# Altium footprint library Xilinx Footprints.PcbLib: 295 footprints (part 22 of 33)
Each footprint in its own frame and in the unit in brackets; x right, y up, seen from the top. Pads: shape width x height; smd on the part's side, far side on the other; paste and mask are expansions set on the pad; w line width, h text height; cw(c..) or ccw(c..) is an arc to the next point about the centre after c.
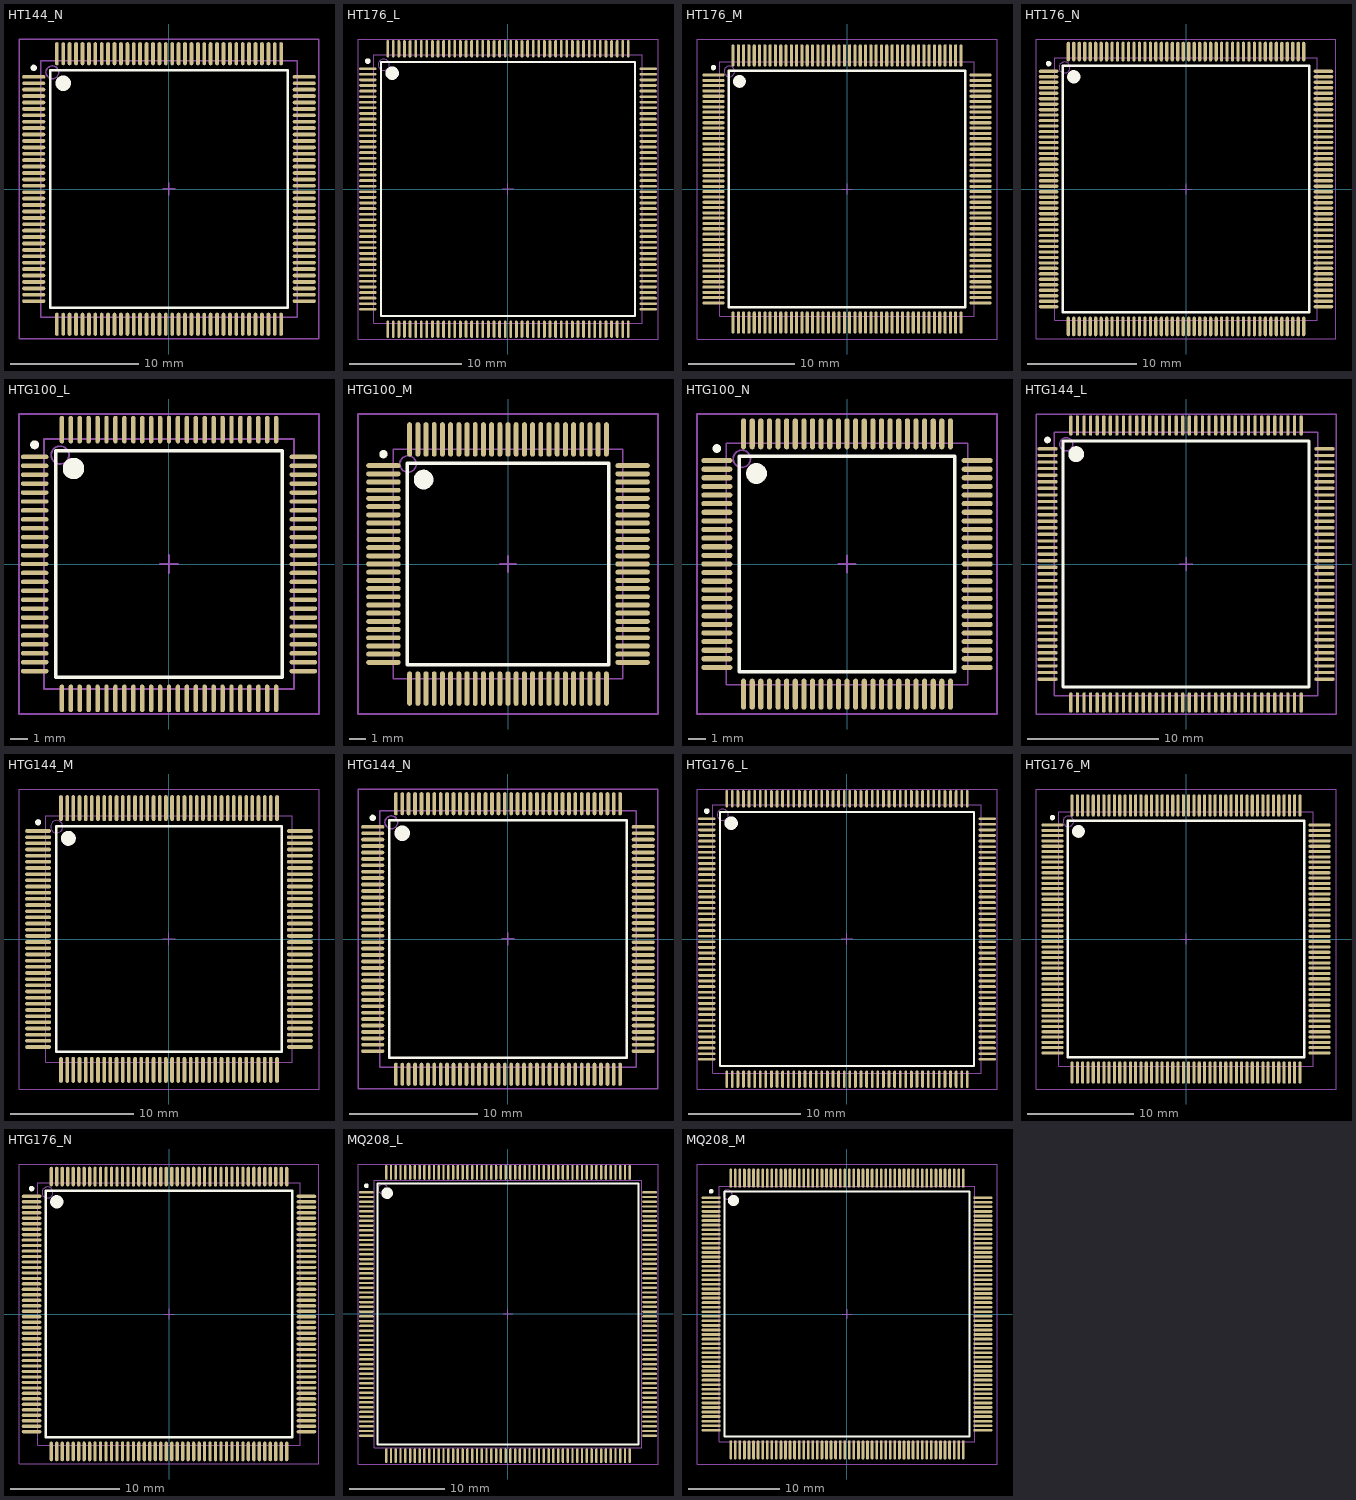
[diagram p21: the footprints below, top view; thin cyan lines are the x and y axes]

## HT144_N [mm] "144-Pin Heat Sink Thin Quad Flat Pack (HT144), IPC Medium Density"
height 1.6
pads (144):
  oval 1.8x0.3 smd: 1(-10.55,8.75) 2(-10.55,8.25) 3(-10.55,7.75) 4(-10.55,7.25) 5(-10.55,6.75) 6(-10.55,6.25) 7(-10.55,5.75) 8(-10.55,5.25) 9(-10.55,4.75) 10(-10.55,4.25) 11(-10.55,3.75) 12(-10.55,3.25) 13(-10.55,2.75) 14(-10.55,2.25) 15(-10.55,1.75) 16(-10.55,1.25) 17(-10.55,0.75) 18(-10.55,0.25) 19(-10.55,-0.25) 20(-10.55,-0.75) 21(-10.55,-1.25) 22(-10.55,-1.75) 23(-10.55,-2.25) 24(-10.55,-2.75) 25(-10.55,-3.25) 26(-10.55,-3.75) 27(-10.55,-4.25) 28(-10.55,-4.75) 29(-10.55,-5.25) 30(-10.55,-5.75) 31(-10.55,-6.25) 32(-10.55,-6.75) 33(-10.55,-7.25) 34(-10.55,-7.75) 35(-10.55,-8.25) 36(-10.55,-8.75) 73(10.55,-8.75) 74(10.55,-8.25) 75(10.55,-7.75) 76(10.55,-7.25) 77(10.55,-6.75) 78(10.55,-6.25) 79(10.55,-5.75) 80(10.55,-5.25) 81(10.55,-4.75) 82(10.55,-4.25) 83(10.55,-3.75) 84(10.55,-3.25) 85(10.55,-2.75) 86(10.55,-2.25) 87(10.55,-1.75) 88(10.55,-1.25) 89(10.55,-0.75) 90(10.55,-0.25) 91(10.55,0.25) 92(10.55,0.75) 93(10.55,1.25) 94(10.55,1.75) 95(10.55,2.25) 96(10.55,2.75) 97(10.55,3.25) 98(10.55,3.75) 99(10.55,4.25) 100(10.55,4.75) 101(10.55,5.25) 102(10.55,5.75) 103(10.55,6.25) 104(10.55,6.75) 105(10.55,7.25) 106(10.55,7.75) 107(10.55,8.25) 108(10.55,8.75)
  oval 0.3x1.8 smd: 37(-8.75,-10.55) 38(-8.25,-10.55) 39(-7.75,-10.55) 40(-7.25,-10.55) 41(-6.75,-10.55) 42(-6.25,-10.55) 43(-5.75,-10.55) 44(-5.25,-10.55) 45(-4.75,-10.55) 46(-4.25,-10.55) 47(-3.75,-10.55) 48(-3.25,-10.55) 49(-2.75,-10.55) 50(-2.25,-10.55) 51(-1.75,-10.55) 52(-1.25,-10.55) 53(-0.75,-10.55) 54(-0.25,-10.55) 55(0.25,-10.55) 56(0.75,-10.55) 57(1.25,-10.55) 58(1.75,-10.55) 59(2.25,-10.55) 60(2.75,-10.55) 61(3.25,-10.55) 62(3.75,-10.55) 63(4.25,-10.55) 64(4.75,-10.55) 65(5.25,-10.55) 66(5.75,-10.55) 67(6.25,-10.55) 68(6.75,-10.55) 69(7.25,-10.55) 70(7.75,-10.55) 71(8.25,-10.55) 72(8.75,-10.55) 109(8.75,10.55) 110(8.25,10.55) 111(7.75,10.55) 112(7.25,10.55) 113(6.75,10.55) 114(6.25,10.55) 115(5.75,10.55) 116(5.25,10.55) 117(4.75,10.55) 118(4.25,10.55) 119(3.75,10.55) 120(3.25,10.55) 121(2.75,10.55) 122(2.25,10.55) 123(1.75,10.55) 124(1.25,10.55) 125(0.75,10.55) 126(0.25,10.55) 127(-0.25,10.55) 128(-0.75,10.55) 129(-1.25,10.55) 130(-1.75,10.55) 131(-2.25,10.55) 132(-2.75,10.55) 133(-3.25,10.55) 134(-3.75,10.55) 135(-4.25,10.55) 136(-4.75,10.55) 137(-5.25,10.55) 138(-5.75,10.55) 139(-6.25,10.55) 140(-6.75,10.55) 141(-7.25,10.55) 142(-7.75,10.55) 143(-8.25,10.55) 144(-8.75,10.55)
Top Overlay:
  circle w0.25: c-10.55,9.45 r0.125
  circle w0.6: c-8.25,8.25 r0.3
  lines w0.2: -9.25,-9.25 -9.25,9.25 9.25,9.25 9.25,-9.25 -9.25,-9.25
Mechanical 13:
  circle w0.1: c-9.1,9.1 r0.5
  lines w0.1: -10,-10 -10,10 10,10 10,-10 -10,-10
Mechanical 15:
  lines w0.1: -0.5,0 0.5,0 ; 0,-0.5 0,0.5 ; -11.7,-11.7 -11.7,11.7 11.7,11.7 11.7,-11.7 -11.7,-11.7
3D body: height 1.6, standoff 0, extent -10,-10 10,10

## HT176_L [mm] "176-Pin Heat Sink Thin Quad Flat Pack (HT176), IPC High Density"
height 1.6
pads (176):
  oval 1.55x0.25 smd: 1(-12.525,10.75) 2(-12.525,10.25) 3(-12.525,9.75) 4(-12.525,9.25) 5(-12.525,8.75) 6(-12.525,8.25) 7(-12.525,7.75) 8(-12.525,7.25) 9(-12.525,6.75) 10(-12.525,6.25) 11(-12.525,5.75) 12(-12.525,5.25) 13(-12.525,4.75) 14(-12.525,4.25) 15(-12.525,3.75) 16(-12.525,3.25) 17(-12.525,2.75) 18(-12.525,2.25) 19(-12.525,1.75) 20(-12.525,1.25) 21(-12.525,0.75) 22(-12.525,0.25) 23(-12.525,-0.25) 24(-12.525,-0.75) 25(-12.525,-1.25) 26(-12.525,-1.75) 27(-12.525,-2.25) 28(-12.525,-2.75) 29(-12.525,-3.25) 30(-12.525,-3.75) 31(-12.525,-4.25) 32(-12.525,-4.75) 33(-12.525,-5.25) 34(-12.525,-5.75) 35(-12.525,-6.25) 36(-12.525,-6.75) 37(-12.525,-7.25) 38(-12.525,-7.75) 39(-12.525,-8.25) 40(-12.525,-8.75) 41(-12.525,-9.25) 42(-12.525,-9.75) 43(-12.525,-10.25) 44(-12.525,-10.75) 89(12.525,-10.75) 90(12.525,-10.25) 91(12.525,-9.75) 92(12.525,-9.25) 93(12.525,-8.75) 94(12.525,-8.25) 95(12.525,-7.75) 96(12.525,-7.25) 97(12.525,-6.75) 98(12.525,-6.25) 99(12.525,-5.75) 100(12.525,-5.25) 101(12.525,-4.75) 102(12.525,-4.25) 103(12.525,-3.75) 104(12.525,-3.25) 105(12.525,-2.75) 106(12.525,-2.25) 107(12.525,-1.75) 108(12.525,-1.25) 109(12.525,-0.75) 110(12.525,-0.25) 111(12.525,0.25) 112(12.525,0.75) 113(12.525,1.25) 114(12.525,1.75) 115(12.525,2.25) 116(12.525,2.75) 117(12.525,3.25) 118(12.525,3.75) 119(12.525,4.25) 120(12.525,4.75) 121(12.525,5.25) 122(12.525,5.75) 123(12.525,6.25) 124(12.525,6.75) 125(12.525,7.25) 126(12.525,7.75) 127(12.525,8.25) 128(12.525,8.75) 129(12.525,9.25) 130(12.525,9.75) 131(12.525,10.25) 132(12.525,10.75)
  oval 0.25x1.55 smd: 45(-10.75,-12.525) 46(-10.25,-12.525) 47(-9.75,-12.525) 48(-9.25,-12.525) 49(-8.75,-12.525) 50(-8.25,-12.525) 51(-7.75,-12.525) 52(-7.25,-12.525) 53(-6.75,-12.525) 54(-6.25,-12.525) 55(-5.75,-12.525) 56(-5.25,-12.525) 57(-4.75,-12.525) 58(-4.25,-12.525) 59(-3.75,-12.525) 60(-3.25,-12.525) 61(-2.75,-12.525) 62(-2.25,-12.525) 63(-1.75,-12.525) 64(-1.25,-12.525) 65(-0.75,-12.525) 66(-0.25,-12.525) 67(0.25,-12.525) 68(0.75,-12.525) 69(1.25,-12.525) 70(1.75,-12.525) 71(2.25,-12.525) 72(2.75,-12.525) 73(3.25,-12.525) 74(3.75,-12.525) 75(4.25,-12.525) 76(4.75,-12.525) 77(5.25,-12.525) 78(5.75,-12.525) 79(6.25,-12.525) 80(6.75,-12.525) 81(7.25,-12.525) 82(7.75,-12.525) 83(8.25,-12.525) 84(8.75,-12.525) 85(9.25,-12.525) 86(9.75,-12.525) 87(10.25,-12.525) 88(10.75,-12.525) 133(10.75,12.525) 134(10.25,12.525) 135(9.75,12.525) 136(9.25,12.525) 137(8.75,12.525) 138(8.25,12.525) 139(7.75,12.525) 140(7.25,12.525) 141(6.75,12.525) 142(6.25,12.525) 143(5.75,12.525) 144(5.25,12.525) 145(4.75,12.525) 146(4.25,12.525) 147(3.75,12.525) 148(3.25,12.525) 149(2.75,12.525) 150(2.25,12.525) 151(1.75,12.525) 152(1.25,12.525) 153(0.75,12.525) 154(0.25,12.525) 155(-0.25,12.525) 156(-0.75,12.525) 157(-1.25,12.525) 158(-1.75,12.525) 159(-2.25,12.525) 160(-2.75,12.525) 161(-3.25,12.525) 162(-3.75,12.525) 163(-4.25,12.525) 164(-4.75,12.525) 165(-5.25,12.525) 166(-5.75,12.525) 167(-6.25,12.525) 168(-6.75,12.525) 169(-7.25,12.525) 170(-7.75,12.525) 171(-8.25,12.525) 172(-8.75,12.525) 173(-9.25,12.525) 174(-9.75,12.525) 175(-10.25,12.525) 176(-10.75,12.525)
Top Overlay:
  circle w0.6: c-10.35,10.35 r0.3
  circle w0.25: c-12.525,11.425 r0.125
  lines w0.2: -11.35,-11.35 11.35,-11.35 11.35,11.35 -11.35,11.35 -11.35,-11.35
Mechanical 13:
  circle w0.1: c-11.1,11.1 r0.5
  lines w0.1: -12,-12 12,-12 12,12 -12,12 -12,-12
Mechanical 15:
  lines w0.1: -0.5,0 0.5,0 ; 0,-0.5 0,0.5 ; -13.4,-13.4 13.4,-13.4 13.4,13.4 -13.4,13.4 -13.4,-13.4
3D body: height 1.6, standoff 0, extent -12,-12 12,12

## HT176_M [mm] "176-Pin Heat Sink Thin Quad Flat Pack (HT176), IPC Low Density"
height 1.6
pads (176):
  oval 2.1x0.3 smd: 1(-12.6,10.75) 2(-12.6,10.25) 3(-12.6,9.75) 4(-12.6,9.25) 5(-12.6,8.75) 6(-12.6,8.25) 7(-12.6,7.75) 8(-12.6,7.25) 9(-12.6,6.75) 10(-12.6,6.25) 11(-12.6,5.75) 12(-12.6,5.25) 13(-12.6,4.75) 14(-12.6,4.25) 15(-12.6,3.75) 16(-12.6,3.25) 17(-12.6,2.75) 18(-12.6,2.25) 19(-12.6,1.75) 20(-12.6,1.25) 21(-12.6,0.75) 22(-12.6,0.25) 23(-12.6,-0.25) 24(-12.6,-0.75) 25(-12.6,-1.25) 26(-12.6,-1.75) 27(-12.6,-2.25) 28(-12.6,-2.75) 29(-12.6,-3.25) 30(-12.6,-3.75) 31(-12.6,-4.25) 32(-12.6,-4.75) 33(-12.6,-5.25) 34(-12.6,-5.75) 35(-12.6,-6.25) 36(-12.6,-6.75) 37(-12.6,-7.25) 38(-12.6,-7.75) 39(-12.6,-8.25) 40(-12.6,-8.75) 41(-12.6,-9.25) 42(-12.6,-9.75) 43(-12.6,-10.25) 44(-12.6,-10.75) 89(12.6,-10.75) 90(12.6,-10.25) 91(12.6,-9.75) 92(12.6,-9.25) 93(12.6,-8.75) 94(12.6,-8.25) 95(12.6,-7.75) 96(12.6,-7.25) 97(12.6,-6.75) 98(12.6,-6.25) 99(12.6,-5.75) 100(12.6,-5.25) 101(12.6,-4.75) 102(12.6,-4.25) 103(12.6,-3.75) 104(12.6,-3.25) 105(12.6,-2.75) 106(12.6,-2.25) 107(12.6,-1.75) 108(12.6,-1.25) 109(12.6,-0.75) 110(12.6,-0.25) 111(12.6,0.25) 112(12.6,0.75) 113(12.6,1.25) 114(12.6,1.75) 115(12.6,2.25) 116(12.6,2.75) 117(12.6,3.25) 118(12.6,3.75) 119(12.6,4.25) 120(12.6,4.75) 121(12.6,5.25) 122(12.6,5.75) 123(12.6,6.25) 124(12.6,6.75) 125(12.6,7.25) 126(12.6,7.75) 127(12.6,8.25) 128(12.6,8.75) 129(12.6,9.25) 130(12.6,9.75) 131(12.6,10.25) 132(12.6,10.75)
  oval 0.3x2.1 smd: 45(-10.75,-12.6) 46(-10.25,-12.6) 47(-9.75,-12.6) 48(-9.25,-12.6) 49(-8.75,-12.6) 50(-8.25,-12.6) 51(-7.75,-12.6) 52(-7.25,-12.6) 53(-6.75,-12.6) 54(-6.25,-12.6) 55(-5.75,-12.6) 56(-5.25,-12.6) 57(-4.75,-12.6) 58(-4.25,-12.6) 59(-3.75,-12.6) 60(-3.25,-12.6) 61(-2.75,-12.6) 62(-2.25,-12.6) 63(-1.75,-12.6) 64(-1.25,-12.6) 65(-0.75,-12.6) 66(-0.25,-12.6) 67(0.25,-12.6) 68(0.75,-12.6) 69(1.25,-12.6) 70(1.75,-12.6) 71(2.25,-12.6) 72(2.75,-12.6) 73(3.25,-12.6) 74(3.75,-12.6) 75(4.25,-12.6) 76(4.75,-12.6) 77(5.25,-12.6) 78(5.75,-12.6) 79(6.25,-12.6) 80(6.75,-12.6) 81(7.25,-12.6) 82(7.75,-12.6) 83(8.25,-12.6) 84(8.75,-12.6) 85(9.25,-12.6) 86(9.75,-12.6) 87(10.25,-12.6) 88(10.75,-12.6) 133(10.75,12.6) 134(10.25,12.6) 135(9.75,12.6) 136(9.25,12.6) 137(8.75,12.6) 138(8.25,12.6) 139(7.75,12.6) 140(7.25,12.6) 141(6.75,12.6) 142(6.25,12.6) 143(5.75,12.6) 144(5.25,12.6) 145(4.75,12.6) 146(4.25,12.6) 147(3.75,12.6) 148(3.25,12.6) 149(2.75,12.6) 150(2.25,12.6) 151(1.75,12.6) 152(1.25,12.6) 153(0.75,12.6) 154(0.25,12.6) 155(-0.25,12.6) 156(-0.75,12.6) 157(-1.25,12.6) 158(-1.75,12.6) 159(-2.25,12.6) 160(-2.75,12.6) 161(-3.25,12.6) 162(-3.75,12.6) 163(-4.25,12.6) 164(-4.75,12.6) 165(-5.25,12.6) 166(-5.75,12.6) 167(-6.25,12.6) 168(-6.75,12.6) 169(-7.25,12.6) 170(-7.75,12.6) 171(-8.25,12.6) 172(-8.75,12.6) 173(-9.25,12.6) 174(-9.75,12.6) 175(-10.25,12.6) 176(-10.75,12.6)
Top Overlay:
  circle w0.6: c-10.15,10.15 r0.3
  circle w0.25: c-12.6,11.45 r0.125
  lines w0.2: -11.15,-11.15 11.15,-11.15 11.15,11.15 -11.15,11.15 -11.15,-11.15
Mechanical 13:
  circle w0.1: c-11.1,11.1 r0.5
  lines w0.1: -12,-12 12,-12 12,12 -12,12 -12,-12
Mechanical 15:
  lines w0.1: -0.5,0 0.5,0 ; 0,-0.5 0,0.5 ; -14.15,-14.15 14.15,-14.15 14.15,14.15 -14.15,14.15 -14.15,-14.15
3D body: height 1.6, standoff 0, extent -12,-12 12,12

## HT176_N [mm] "176-Pin Heat Sink Thin Quad Flat Pack (HT176), IPC Medium Density"
height 1.6
pads (176):
  oval 1.8x0.3 smd: 1(-12.55,10.75) 2(-12.55,10.25) 3(-12.55,9.75) 4(-12.55,9.25) 5(-12.55,8.75) 6(-12.55,8.25) 7(-12.55,7.75) 8(-12.55,7.25) 9(-12.55,6.75) 10(-12.55,6.25) 11(-12.55,5.75) 12(-12.55,5.25) 13(-12.55,4.75) 14(-12.55,4.25) 15(-12.55,3.75) 16(-12.55,3.25) 17(-12.55,2.75) 18(-12.55,2.25) 19(-12.55,1.75) 20(-12.55,1.25) 21(-12.55,0.75) 22(-12.55,0.25) 23(-12.55,-0.25) 24(-12.55,-0.75) 25(-12.55,-1.25) 26(-12.55,-1.75) 27(-12.55,-2.25) 28(-12.55,-2.75) 29(-12.55,-3.25) 30(-12.55,-3.75) 31(-12.55,-4.25) 32(-12.55,-4.75) 33(-12.55,-5.25) 34(-12.55,-5.75) 35(-12.55,-6.25) 36(-12.55,-6.75) 37(-12.55,-7.25) 38(-12.55,-7.75) 39(-12.55,-8.25) 40(-12.55,-8.75) 41(-12.55,-9.25) 42(-12.55,-9.75) 43(-12.55,-10.25) 44(-12.55,-10.75) 89(12.55,-10.75) 90(12.55,-10.25) 91(12.55,-9.75) 92(12.55,-9.25) 93(12.55,-8.75) 94(12.55,-8.25) 95(12.55,-7.75) 96(12.55,-7.25) 97(12.55,-6.75) 98(12.55,-6.25) 99(12.55,-5.75) 100(12.55,-5.25) 101(12.55,-4.75) 102(12.55,-4.25) 103(12.55,-3.75) 104(12.55,-3.25) 105(12.55,-2.75) 106(12.55,-2.25) 107(12.55,-1.75) 108(12.55,-1.25) 109(12.55,-0.75) 110(12.55,-0.25) 111(12.55,0.25) 112(12.55,0.75) 113(12.55,1.25) 114(12.55,1.75) 115(12.55,2.25) 116(12.55,2.75) 117(12.55,3.25) 118(12.55,3.75) 119(12.55,4.25) 120(12.55,4.75) 121(12.55,5.25) 122(12.55,5.75) 123(12.55,6.25) 124(12.55,6.75) 125(12.55,7.25) 126(12.55,7.75) 127(12.55,8.25) 128(12.55,8.75) 129(12.55,9.25) 130(12.55,9.75) 131(12.55,10.25) 132(12.55,10.75)
  oval 0.3x1.8 smd: 45(-10.75,-12.55) 46(-10.25,-12.55) 47(-9.75,-12.55) 48(-9.25,-12.55) 49(-8.75,-12.55) 50(-8.25,-12.55) 51(-7.75,-12.55) 52(-7.25,-12.55) 53(-6.75,-12.55) 54(-6.25,-12.55) 55(-5.75,-12.55) 56(-5.25,-12.55) 57(-4.75,-12.55) 58(-4.25,-12.55) 59(-3.75,-12.55) 60(-3.25,-12.55) 61(-2.75,-12.55) 62(-2.25,-12.55) 63(-1.75,-12.55) 64(-1.25,-12.55) 65(-0.75,-12.55) 66(-0.25,-12.55) 67(0.25,-12.55) 68(0.75,-12.55) 69(1.25,-12.55) 70(1.75,-12.55) 71(2.25,-12.55) 72(2.75,-12.55) 73(3.25,-12.55) 74(3.75,-12.55) 75(4.25,-12.55) 76(4.75,-12.55) 77(5.25,-12.55) 78(5.75,-12.55) 79(6.25,-12.55) 80(6.75,-12.55) 81(7.25,-12.55) 82(7.75,-12.55) 83(8.25,-12.55) 84(8.75,-12.55) 85(9.25,-12.55) 86(9.75,-12.55) 87(10.25,-12.55) 88(10.75,-12.55) 133(10.75,12.55) 134(10.25,12.55) 135(9.75,12.55) 136(9.25,12.55) 137(8.75,12.55) 138(8.25,12.55) 139(7.75,12.55) 140(7.25,12.55) 141(6.75,12.55) 142(6.25,12.55) 143(5.75,12.55) 144(5.25,12.55) 145(4.75,12.55) 146(4.25,12.55) 147(3.75,12.55) 148(3.25,12.55) 149(2.75,12.55) 150(2.25,12.55) 151(1.75,12.55) 152(1.25,12.55) 153(0.75,12.55) 154(0.25,12.55) 155(-0.25,12.55) 156(-0.75,12.55) 157(-1.25,12.55) 158(-1.75,12.55) 159(-2.25,12.55) 160(-2.75,12.55) 161(-3.25,12.55) 162(-3.75,12.55) 163(-4.25,12.55) 164(-4.75,12.55) 165(-5.25,12.55) 166(-5.75,12.55) 167(-6.25,12.55) 168(-6.75,12.55) 169(-7.25,12.55) 170(-7.75,12.55) 171(-8.25,12.55) 172(-8.75,12.55) 173(-9.25,12.55) 174(-9.75,12.55) 175(-10.25,12.55) 176(-10.75,12.55)
Top Overlay:
  circle w0.25: c-12.55,11.45 r0.125
  circle w0.6: c-10.25,10.25 r0.3
  lines w0.2: -11.25,-11.25 -11.25,11.25 11.25,11.25 11.25,-11.25 -11.25,-11.25
Mechanical 13:
  circle w0.1: c-11.1,11.1 r0.5
  lines w0.1: -12,-12 -12,12 12,12 12,-12 -12,-12
Mechanical 15:
  lines w0.1: -0.5,0 0.5,0 ; 0,-0.5 0,0.5 ; -13.7,-13.7 -13.7,13.7 13.7,13.7 13.7,-13.7 -13.7,-13.7
3D body: height 1.6, standoff 0, extent -12,-12 12,12

## HTG100_L [mm] "100-Pin Heat Sink Thin Quad Flat Pack (HTG100) - Pb-Free, IPC High Density"
height 1.6
pads (100):
  oval 1.55x0.25 smd: 1(-7.525,6) 2(-7.525,5.5) 3(-7.525,5) 4(-7.525,4.5) 5(-7.525,4) 6(-7.525,3.5) 7(-7.525,3) 8(-7.525,2.5) 9(-7.525,2) 10(-7.525,1.5) 11(-7.525,1) 12(-7.525,0.5) 13(-7.525,0) 14(-7.525,-0.5) 15(-7.525,-1) 16(-7.525,-1.5) 17(-7.525,-2) 18(-7.525,-2.5) 19(-7.525,-3) 20(-7.525,-3.5) 21(-7.525,-4) 22(-7.525,-4.5) 23(-7.525,-5) 24(-7.525,-5.5) 25(-7.525,-6) 51(7.525,-6) 52(7.525,-5.5) 53(7.525,-5) 54(7.525,-4.5) 55(7.525,-4) 56(7.525,-3.5) 57(7.525,-3) 58(7.525,-2.5) 59(7.525,-2) 60(7.525,-1.5) 61(7.525,-1) 62(7.525,-0.5) 63(7.525,0) 64(7.525,0.5) 65(7.525,1) 66(7.525,1.5) 67(7.525,2) 68(7.525,2.5) 69(7.525,3) 70(7.525,3.5) 71(7.525,4) 72(7.525,4.5) 73(7.525,5) 74(7.525,5.5) 75(7.525,6)
  oval 0.25x1.55 smd: 26(-6,-7.525) 27(-5.5,-7.525) 28(-5,-7.525) 29(-4.5,-7.525) 30(-4,-7.525) 31(-3.5,-7.525) 32(-3,-7.525) 33(-2.5,-7.525) 34(-2,-7.525) 35(-1.5,-7.525) 36(-1,-7.525) 37(-0.5,-7.525) 38(0,-7.525) 39(0.5,-7.525) 40(1,-7.525) 41(1.5,-7.525) 42(2,-7.525) 43(2.5,-7.525) 44(3,-7.525) 45(3.5,-7.525) 46(4,-7.525) 47(4.5,-7.525) 48(5,-7.525) 49(5.5,-7.525) 50(6,-7.525) 76(6,7.525) 77(5.5,7.525) 78(5,7.525) 79(4.5,7.525) 80(4,7.525) 81(3.5,7.525) 82(3,7.525) 83(2.5,7.525) 84(2,7.525) 85(1.5,7.525) 86(1,7.525) 87(0.5,7.525) 88(0,7.525) 89(-0.5,7.525) 90(-1,7.525) 91(-1.5,7.525) 92(-2,7.525) 93(-2.5,7.525) 94(-3,7.525) 95(-3.5,7.525) 96(-4,7.525) 97(-4.5,7.525) 98(-5,7.525) 99(-5.5,7.525) 100(-6,7.525)
Top Overlay:
  circle w0.6: c-5.35,5.35 r0.3
  circle w0.25: c-7.525,6.675 r0.125
  lines w0.2: -6.35,-6.35 6.35,-6.35 6.35,6.35 -6.35,6.35 -6.35,-6.35
Mechanical 13:
  circle w0.1: c-6.1,6.1 r0.5
  lines w0.1: -7,-7 7,-7 7,7 -7,7 -7,-7
Mechanical 15:
  lines w0.1: -0.5,0 0.5,0 ; 0,-0.5 0,0.5 ; -8.4,-8.4 8.4,-8.4 8.4,8.4 -8.4,8.4 -8.4,-8.4
3D body: height 1.6, standoff 0, extent -7,-7 7,7

## HTG100_M [mm] "100-Pin Heat Sink Thin Quad Flat Pack (HTG100) - Pb-Free, IPC Low Density"
height 1.6
pads (100):
  oval 2.1x0.3 smd: 1(-7.6,6) 2(-7.6,5.5) 3(-7.6,5) 4(-7.6,4.5) 5(-7.6,4) 6(-7.6,3.5) 7(-7.6,3) 8(-7.6,2.5) 9(-7.6,2) 10(-7.6,1.5) 11(-7.6,1) 12(-7.6,0.5) 13(-7.6,0) 14(-7.6,-0.5) 15(-7.6,-1) 16(-7.6,-1.5) 17(-7.6,-2) 18(-7.6,-2.5) 19(-7.6,-3) 20(-7.6,-3.5) 21(-7.6,-4) 22(-7.6,-4.5) 23(-7.6,-5) 24(-7.6,-5.5) 25(-7.6,-6) 51(7.6,-6) 52(7.6,-5.5) 53(7.6,-5) 54(7.6,-4.5) 55(7.6,-4) 56(7.6,-3.5) 57(7.6,-3) 58(7.6,-2.5) 59(7.6,-2) 60(7.6,-1.5) 61(7.6,-1) 62(7.6,-0.5) 63(7.6,0) 64(7.6,0.5) 65(7.6,1) 66(7.6,1.5) 67(7.6,2) 68(7.6,2.5) 69(7.6,3) 70(7.6,3.5) 71(7.6,4) 72(7.6,4.5) 73(7.6,5) 74(7.6,5.5) 75(7.6,6)
  oval 0.3x2.1 smd: 26(-6,-7.6) 27(-5.5,-7.6) 28(-5,-7.6) 29(-4.5,-7.6) 30(-4,-7.6) 31(-3.5,-7.6) 32(-3,-7.6) 33(-2.5,-7.6) 34(-2,-7.6) 35(-1.5,-7.6) 36(-1,-7.6) 37(-0.5,-7.6) 38(0,-7.6) 39(0.5,-7.6) 40(1,-7.6) 41(1.5,-7.6) 42(2,-7.6) 43(2.5,-7.6) 44(3,-7.6) 45(3.5,-7.6) 46(4,-7.6) 47(4.5,-7.6) 48(5,-7.6) 49(5.5,-7.6) 50(6,-7.6) 76(6,7.6) 77(5.5,7.6) 78(5,7.6) 79(4.5,7.6) 80(4,7.6) 81(3.5,7.6) 82(3,7.6) 83(2.5,7.6) 84(2,7.6) 85(1.5,7.6) 86(1,7.6) 87(0.5,7.6) 88(0,7.6) 89(-0.5,7.6) 90(-1,7.6) 91(-1.5,7.6) 92(-2,7.6) 93(-2.5,7.6) 94(-3,7.6) 95(-3.5,7.6) 96(-4,7.6) 97(-4.5,7.6) 98(-5,7.6) 99(-5.5,7.6) 100(-6,7.6)
Top Overlay:
  circle w0.6: c-5.15,5.15 r0.3
  circle w0.25: c-7.6,6.7 r0.125
  lines w0.2: -6.15,-6.15 6.15,-6.15 6.15,6.15 -6.15,6.15 -6.15,-6.15
Mechanical 13:
  circle w0.1: c-6.1,6.1 r0.5
  lines w0.1: -7,-7 7,-7 7,7 -7,7 -7,-7
Mechanical 15:
  lines w0.1: -0.5,0 0.5,0 ; 0,-0.5 0,0.5 ; -9.15,-9.15 9.15,-9.15 9.15,9.15 -9.15,9.15 -9.15,-9.15
3D body: height 1.6, standoff 0, extent -7,-7 7,7

## HTG100_N [mm] "100-Pin Heat Sink Thin Quad Flat Pack (HTG100) - Pb-Free, IPC Medium Density"
height 1.6
pads (100):
  oval 1.8x0.3 smd: 1(-7.55,6) 2(-7.55,5.5) 3(-7.55,5) 4(-7.55,4.5) 5(-7.55,4) 6(-7.55,3.5) 7(-7.55,3) 8(-7.55,2.5) 9(-7.55,2) 10(-7.55,1.5) 11(-7.55,1) 12(-7.55,0.5) 13(-7.55,0) 14(-7.55,-0.5) 15(-7.55,-1) 16(-7.55,-1.5) 17(-7.55,-2) 18(-7.55,-2.5) 19(-7.55,-3) 20(-7.55,-3.5) 21(-7.55,-4) 22(-7.55,-4.5) 23(-7.55,-5) 24(-7.55,-5.5) 25(-7.55,-6) 51(7.55,-6) 52(7.55,-5.5) 53(7.55,-5) 54(7.55,-4.5) 55(7.55,-4) 56(7.55,-3.5) 57(7.55,-3) 58(7.55,-2.5) 59(7.55,-2) 60(7.55,-1.5) 61(7.55,-1) 62(7.55,-0.5) 63(7.55,0) 64(7.55,0.5) 65(7.55,1) 66(7.55,1.5) 67(7.55,2) 68(7.55,2.5) 69(7.55,3) 70(7.55,3.5) 71(7.55,4) 72(7.55,4.5) 73(7.55,5) 74(7.55,5.5) 75(7.55,6)
  oval 0.3x1.8 smd: 26(-6,-7.55) 27(-5.5,-7.55) 28(-5,-7.55) 29(-4.5,-7.55) 30(-4,-7.55) 31(-3.5,-7.55) 32(-3,-7.55) 33(-2.5,-7.55) 34(-2,-7.55) 35(-1.5,-7.55) 36(-1,-7.55) 37(-0.5,-7.55) 38(0,-7.55) 39(0.5,-7.55) 40(1,-7.55) 41(1.5,-7.55) 42(2,-7.55) 43(2.5,-7.55) 44(3,-7.55) 45(3.5,-7.55) 46(4,-7.55) 47(4.5,-7.55) 48(5,-7.55) 49(5.5,-7.55) 50(6,-7.55) 76(6,7.55) 77(5.5,7.55) 78(5,7.55) 79(4.5,7.55) 80(4,7.55) 81(3.5,7.55) 82(3,7.55) 83(2.5,7.55) 84(2,7.55) 85(1.5,7.55) 86(1,7.55) 87(0.5,7.55) 88(0,7.55) 89(-0.5,7.55) 90(-1,7.55) 91(-1.5,7.55) 92(-2,7.55) 93(-2.5,7.55) 94(-3,7.55) 95(-3.5,7.55) 96(-4,7.55) 97(-4.5,7.55) 98(-5,7.55) 99(-5.5,7.55) 100(-6,7.55)
Top Overlay:
  circle w0.6: c-5.25,5.25 r0.3
  circle w0.25: c-7.55,6.7 r0.125
  lines w0.2: -6.25,-6.25 6.25,-6.25 6.25,6.25 -6.25,6.25 -6.25,-6.25
Mechanical 13:
  circle w0.1: c-6.1,6.1 r0.5
  lines w0.1: -7,-7 7,-7 7,7 -7,7 -7,-7
Mechanical 15:
  lines w0.1: -0.5,0 0.5,0 ; 0,-0.5 0,0.5 ; -8.7,-8.7 8.7,-8.7 8.7,8.7 -8.7,8.7 -8.7,-8.7
3D body: height 1.6, standoff 0, extent -7,-7 7,7

## HTG144_L [mm] "144-Pin Heat Sink Thin Quad Flat Pack (HTG144) - Pb-Free, IPC High Density"
height 1.6
pads (144):
  oval 1.55x0.25 smd: 1(-10.525,8.75) 2(-10.525,8.25) 3(-10.525,7.75) 4(-10.525,7.25) 5(-10.525,6.75) 6(-10.525,6.25) 7(-10.525,5.75) 8(-10.525,5.25) 9(-10.525,4.75) 10(-10.525,4.25) 11(-10.525,3.75) 12(-10.525,3.25) 13(-10.525,2.75) 14(-10.525,2.25) 15(-10.525,1.75) 16(-10.525,1.25) 17(-10.525,0.75) 18(-10.525,0.25) 19(-10.525,-0.25) 20(-10.525,-0.75) 21(-10.525,-1.25) 22(-10.525,-1.75) 23(-10.525,-2.25) 24(-10.525,-2.75) 25(-10.525,-3.25) 26(-10.525,-3.75) 27(-10.525,-4.25) 28(-10.525,-4.75) 29(-10.525,-5.25) 30(-10.525,-5.75) 31(-10.525,-6.25) 32(-10.525,-6.75) 33(-10.525,-7.25) 34(-10.525,-7.75) 35(-10.525,-8.25) 36(-10.525,-8.75) 73(10.525,-8.75) 74(10.525,-8.25) 75(10.525,-7.75) 76(10.525,-7.25) 77(10.525,-6.75) 78(10.525,-6.25) 79(10.525,-5.75) 80(10.525,-5.25) 81(10.525,-4.75) 82(10.525,-4.25) 83(10.525,-3.75) 84(10.525,-3.25) 85(10.525,-2.75) 86(10.525,-2.25) 87(10.525,-1.75) 88(10.525,-1.25) 89(10.525,-0.75) 90(10.525,-0.25) 91(10.525,0.25) 92(10.525,0.75) 93(10.525,1.25) 94(10.525,1.75) 95(10.525,2.25) 96(10.525,2.75) 97(10.525,3.25) 98(10.525,3.75) 99(10.525,4.25) 100(10.525,4.75) 101(10.525,5.25) 102(10.525,5.75) 103(10.525,6.25) 104(10.525,6.75) 105(10.525,7.25) 106(10.525,7.75) 107(10.525,8.25) 108(10.525,8.75)
  oval 0.25x1.55 smd: 37(-8.75,-10.525) 38(-8.25,-10.525) 39(-7.75,-10.525) 40(-7.25,-10.525) 41(-6.75,-10.525) 42(-6.25,-10.525) 43(-5.75,-10.525) 44(-5.25,-10.525) 45(-4.75,-10.525) 46(-4.25,-10.525) 47(-3.75,-10.525) 48(-3.25,-10.525) 49(-2.75,-10.525) 50(-2.25,-10.525) 51(-1.75,-10.525) 52(-1.25,-10.525) 53(-0.75,-10.525) 54(-0.25,-10.525) 55(0.25,-10.525) 56(0.75,-10.525) 57(1.25,-10.525) 58(1.75,-10.525) 59(2.25,-10.525) 60(2.75,-10.525) 61(3.25,-10.525) 62(3.75,-10.525) 63(4.25,-10.525) 64(4.75,-10.525) 65(5.25,-10.525) 66(5.75,-10.525) 67(6.25,-10.525) 68(6.75,-10.525) 69(7.25,-10.525) 70(7.75,-10.525) 71(8.25,-10.525) 72(8.75,-10.525) 109(8.75,10.525) 110(8.25,10.525) 111(7.75,10.525) 112(7.25,10.525) 113(6.75,10.525) 114(6.25,10.525) 115(5.75,10.525) 116(5.25,10.525) 117(4.75,10.525) 118(4.25,10.525) 119(3.75,10.525) 120(3.25,10.525) 121(2.75,10.525) 122(2.25,10.525) 123(1.75,10.525) 124(1.25,10.525) 125(0.75,10.525) 126(0.25,10.525) 127(-0.25,10.525) 128(-0.75,10.525) 129(-1.25,10.525) 130(-1.75,10.525) 131(-2.25,10.525) 132(-2.75,10.525) 133(-3.25,10.525) 134(-3.75,10.525) 135(-4.25,10.525) 136(-4.75,10.525) 137(-5.25,10.525) 138(-5.75,10.525) 139(-6.25,10.525) 140(-6.75,10.525) 141(-7.25,10.525) 142(-7.75,10.525) 143(-8.25,10.525) 144(-8.75,10.525)
Top Overlay:
  circle w0.6: c-8.35,8.35 r0.3
  circle w0.25: c-10.525,9.425 r0.125
  lines w0.2: -9.35,-9.35 9.35,-9.35 9.35,9.35 -9.35,9.35 -9.35,-9.35
Mechanical 13:
  circle w0.1: c-9.1,9.1 r0.5
  lines w0.1: -10,-10 10,-10 10,10 -10,10 -10,-10
Mechanical 15:
  lines w0.1: -0.5,0 0.5,0 ; 0,-0.5 0,0.5 ; -11.4,-11.4 11.4,-11.4 11.4,11.4 -11.4,11.4 -11.4,-11.4
3D body: height 1.6, standoff 0, extent -10,-10 10,10

## HTG144_M [mm] "144-Pin Heat Sink Thin Quad Flat Pack (HTG144) - Pb-Free, IPC Low Density"
height 1.6
pads (144):
  oval 2.1x0.3 smd: 1(-10.6,8.75) 2(-10.6,8.25) 3(-10.6,7.75) 4(-10.6,7.25) 5(-10.6,6.75) 6(-10.6,6.25) 7(-10.6,5.75) 8(-10.6,5.25) 9(-10.6,4.75) 10(-10.6,4.25) 11(-10.6,3.75) 12(-10.6,3.25) 13(-10.6,2.75) 14(-10.6,2.25) 15(-10.6,1.75) 16(-10.6,1.25) 17(-10.6,0.75) 18(-10.6,0.25) 19(-10.6,-0.25) 20(-10.6,-0.75) 21(-10.6,-1.25) 22(-10.6,-1.75) 23(-10.6,-2.25) 24(-10.6,-2.75) 25(-10.6,-3.25) 26(-10.6,-3.75) 27(-10.6,-4.25) 28(-10.6,-4.75) 29(-10.6,-5.25) 30(-10.6,-5.75) 31(-10.6,-6.25) 32(-10.6,-6.75) 33(-10.6,-7.25) 34(-10.6,-7.75) 35(-10.6,-8.25) 36(-10.6,-8.75) 73(10.6,-8.75) 74(10.6,-8.25) 75(10.6,-7.75) 76(10.6,-7.25) 77(10.6,-6.75) 78(10.6,-6.25) 79(10.6,-5.75) 80(10.6,-5.25) 81(10.6,-4.75) 82(10.6,-4.25) 83(10.6,-3.75) 84(10.6,-3.25) 85(10.6,-2.75) 86(10.6,-2.25) 87(10.6,-1.75) 88(10.6,-1.25) 89(10.6,-0.75) 90(10.6,-0.25) 91(10.6,0.25) 92(10.6,0.75) 93(10.6,1.25) 94(10.6,1.75) 95(10.6,2.25) 96(10.6,2.75) 97(10.6,3.25) 98(10.6,3.75) 99(10.6,4.25) 100(10.6,4.75) 101(10.6,5.25) 102(10.6,5.75) 103(10.6,6.25) 104(10.6,6.75) 105(10.6,7.25) 106(10.6,7.75) 107(10.6,8.25) 108(10.6,8.75)
  oval 0.3x2.1 smd: 37(-8.75,-10.6) 38(-8.25,-10.6) 39(-7.75,-10.6) 40(-7.25,-10.6) 41(-6.75,-10.6) 42(-6.25,-10.6) 43(-5.75,-10.6) 44(-5.25,-10.6) 45(-4.75,-10.6) 46(-4.25,-10.6) 47(-3.75,-10.6) 48(-3.25,-10.6) 49(-2.75,-10.6) 50(-2.25,-10.6) 51(-1.75,-10.6) 52(-1.25,-10.6) 53(-0.75,-10.6) 54(-0.25,-10.6) 55(0.25,-10.6) 56(0.75,-10.6) 57(1.25,-10.6) 58(1.75,-10.6) 59(2.25,-10.6) 60(2.75,-10.6) 61(3.25,-10.6) 62(3.75,-10.6) 63(4.25,-10.6) 64(4.75,-10.6) 65(5.25,-10.6) 66(5.75,-10.6) 67(6.25,-10.6) 68(6.75,-10.6) 69(7.25,-10.6) 70(7.75,-10.6) 71(8.25,-10.6) 72(8.75,-10.6) 109(8.75,10.6) 110(8.25,10.6) 111(7.75,10.6) 112(7.25,10.6) 113(6.75,10.6) 114(6.25,10.6) 115(5.75,10.6) 116(5.25,10.6) 117(4.75,10.6) 118(4.25,10.6) 119(3.75,10.6) 120(3.25,10.6) 121(2.75,10.6) 122(2.25,10.6) 123(1.75,10.6) 124(1.25,10.6) 125(0.75,10.6) 126(0.25,10.6) 127(-0.25,10.6) 128(-0.75,10.6) 129(-1.25,10.6) 130(-1.75,10.6) 131(-2.25,10.6) 132(-2.75,10.6) 133(-3.25,10.6) 134(-3.75,10.6) 135(-4.25,10.6) 136(-4.75,10.6) 137(-5.25,10.6) 138(-5.75,10.6) 139(-6.25,10.6) 140(-6.75,10.6) 141(-7.25,10.6) 142(-7.75,10.6) 143(-8.25,10.6) 144(-8.75,10.6)
Top Overlay:
  circle w0.6: c-8.15,8.15 r0.3
  circle w0.25: c-10.6,9.45 r0.125
  lines w0.2: -9.15,-9.15 9.15,-9.15 9.15,9.15 -9.15,9.15 -9.15,-9.15
Mechanical 13:
  circle w0.1: c-9.1,9.1 r0.5
  lines w0.1: -10,-10 10,-10 10,10 -10,10 -10,-10
Mechanical 15:
  lines w0.1: -0.5,0 0.5,0 ; 0,-0.5 0,0.5 ; -12.15,-12.15 12.15,-12.15 12.15,12.15 -12.15,12.15 -12.15,-12.15
3D body: height 1.6, standoff 0, extent -10,-10 10,10

## HTG144_N [mm] "144-Pin Heat Sink Thin Quad Flat Pack (HTG144) - Pb-Free, IPC Medium Density"
height 1.6
pads (144):
  oval 1.8x0.3 smd: 1(-10.55,8.75) 2(-10.55,8.25) 3(-10.55,7.75) 4(-10.55,7.25) 5(-10.55,6.75) 6(-10.55,6.25) 7(-10.55,5.75) 8(-10.55,5.25) 9(-10.55,4.75) 10(-10.55,4.25) 11(-10.55,3.75) 12(-10.55,3.25) 13(-10.55,2.75) 14(-10.55,2.25) 15(-10.55,1.75) 16(-10.55,1.25) 17(-10.55,0.75) 18(-10.55,0.25) 19(-10.55,-0.25) 20(-10.55,-0.75) 21(-10.55,-1.25) 22(-10.55,-1.75) 23(-10.55,-2.25) 24(-10.55,-2.75) 25(-10.55,-3.25) 26(-10.55,-3.75) 27(-10.55,-4.25) 28(-10.55,-4.75) 29(-10.55,-5.25) 30(-10.55,-5.75) 31(-10.55,-6.25) 32(-10.55,-6.75) 33(-10.55,-7.25) 34(-10.55,-7.75) 35(-10.55,-8.25) 36(-10.55,-8.75) 73(10.55,-8.75) 74(10.55,-8.25) 75(10.55,-7.75) 76(10.55,-7.25) 77(10.55,-6.75) 78(10.55,-6.25) 79(10.55,-5.75) 80(10.55,-5.25) 81(10.55,-4.75) 82(10.55,-4.25) 83(10.55,-3.75) 84(10.55,-3.25) 85(10.55,-2.75) 86(10.55,-2.25) 87(10.55,-1.75) 88(10.55,-1.25) 89(10.55,-0.75) 90(10.55,-0.25) 91(10.55,0.25) 92(10.55,0.75) 93(10.55,1.25) 94(10.55,1.75) 95(10.55,2.25) 96(10.55,2.75) 97(10.55,3.25) 98(10.55,3.75) 99(10.55,4.25) 100(10.55,4.75) 101(10.55,5.25) 102(10.55,5.75) 103(10.55,6.25) 104(10.55,6.75) 105(10.55,7.25) 106(10.55,7.75) 107(10.55,8.25) 108(10.55,8.75)
  oval 0.3x1.8 smd: 37(-8.75,-10.55) 38(-8.25,-10.55) 39(-7.75,-10.55) 40(-7.25,-10.55) 41(-6.75,-10.55) 42(-6.25,-10.55) 43(-5.75,-10.55) 44(-5.25,-10.55) 45(-4.75,-10.55) 46(-4.25,-10.55) 47(-3.75,-10.55) 48(-3.25,-10.55) 49(-2.75,-10.55) 50(-2.25,-10.55) 51(-1.75,-10.55) 52(-1.25,-10.55) 53(-0.75,-10.55) 54(-0.25,-10.55) 55(0.25,-10.55) 56(0.75,-10.55) 57(1.25,-10.55) 58(1.75,-10.55) 59(2.25,-10.55) 60(2.75,-10.55) 61(3.25,-10.55) 62(3.75,-10.55) 63(4.25,-10.55) 64(4.75,-10.55) 65(5.25,-10.55) 66(5.75,-10.55) 67(6.25,-10.55) 68(6.75,-10.55) 69(7.25,-10.55) 70(7.75,-10.55) 71(8.25,-10.55) 72(8.75,-10.55) 109(8.75,10.55) 110(8.25,10.55) 111(7.75,10.55) 112(7.25,10.55) 113(6.75,10.55) 114(6.25,10.55) 115(5.75,10.55) 116(5.25,10.55) 117(4.75,10.55) 118(4.25,10.55) 119(3.75,10.55) 120(3.25,10.55) 121(2.75,10.55) 122(2.25,10.55) 123(1.75,10.55) 124(1.25,10.55) 125(0.75,10.55) 126(0.25,10.55) 127(-0.25,10.55) 128(-0.75,10.55) 129(-1.25,10.55) 130(-1.75,10.55) 131(-2.25,10.55) 132(-2.75,10.55) 133(-3.25,10.55) 134(-3.75,10.55) 135(-4.25,10.55) 136(-4.75,10.55) 137(-5.25,10.55) 138(-5.75,10.55) 139(-6.25,10.55) 140(-6.75,10.55) 141(-7.25,10.55) 142(-7.75,10.55) 143(-8.25,10.55) 144(-8.75,10.55)
Top Overlay:
  circle w0.25: c-10.55,9.45 r0.125
  circle w0.6: c-8.25,8.25 r0.3
  lines w0.2: -9.25,-9.25 -9.25,9.25 9.25,9.25 9.25,-9.25 -9.25,-9.25
Mechanical 13:
  circle w0.1: c-9.1,9.1 r0.5
  lines w0.1: -10,-10 -10,10 10,10 10,-10 -10,-10
Mechanical 15:
  lines w0.1: -0.5,0 0.5,0 ; 0,-0.5 0,0.5 ; -11.7,-11.7 -11.7,11.7 11.7,11.7 11.7,-11.7 -11.7,-11.7
3D body: height 1.6, standoff 0, extent -10,-10 10,10

## HTG176_L [mm] "176-Pin Heat Sink Thin Quad Flat Pack (HTG176) - Pb-Free, IPC High Density"
height 1.6
pads (176):
  oval 1.55x0.25 smd: 1(-12.525,10.75) 2(-12.525,10.25) 3(-12.525,9.75) 4(-12.525,9.25) 5(-12.525,8.75) 6(-12.525,8.25) 7(-12.525,7.75) 8(-12.525,7.25) 9(-12.525,6.75) 10(-12.525,6.25) 11(-12.525,5.75) 12(-12.525,5.25) 13(-12.525,4.75) 14(-12.525,4.25) 15(-12.525,3.75) 16(-12.525,3.25) 17(-12.525,2.75) 18(-12.525,2.25) 19(-12.525,1.75) 20(-12.525,1.25) 21(-12.525,0.75) 22(-12.525,0.25) 23(-12.525,-0.25) 24(-12.525,-0.75) 25(-12.525,-1.25) 26(-12.525,-1.75) 27(-12.525,-2.25) 28(-12.525,-2.75) 29(-12.525,-3.25) 30(-12.525,-3.75) 31(-12.525,-4.25) 32(-12.525,-4.75) 33(-12.525,-5.25) 34(-12.525,-5.75) 35(-12.525,-6.25) 36(-12.525,-6.75) 37(-12.525,-7.25) 38(-12.525,-7.75) 39(-12.525,-8.25) 40(-12.525,-8.75) 41(-12.525,-9.25) 42(-12.525,-9.75) 43(-12.525,-10.25) 44(-12.525,-10.75) 89(12.525,-10.75) 90(12.525,-10.25) 91(12.525,-9.75) 92(12.525,-9.25) 93(12.525,-8.75) 94(12.525,-8.25) 95(12.525,-7.75) 96(12.525,-7.25) 97(12.525,-6.75) 98(12.525,-6.25) 99(12.525,-5.75) 100(12.525,-5.25) 101(12.525,-4.75) 102(12.525,-4.25) 103(12.525,-3.75) 104(12.525,-3.25) 105(12.525,-2.75) 106(12.525,-2.25) 107(12.525,-1.75) 108(12.525,-1.25) 109(12.525,-0.75) 110(12.525,-0.25) 111(12.525,0.25) 112(12.525,0.75) 113(12.525,1.25) 114(12.525,1.75) 115(12.525,2.25) 116(12.525,2.75) 117(12.525,3.25) 118(12.525,3.75) 119(12.525,4.25) 120(12.525,4.75) 121(12.525,5.25) 122(12.525,5.75) 123(12.525,6.25) 124(12.525,6.75) 125(12.525,7.25) 126(12.525,7.75) 127(12.525,8.25) 128(12.525,8.75) 129(12.525,9.25) 130(12.525,9.75) 131(12.525,10.25) 132(12.525,10.75)
  oval 0.25x1.55 smd: 45(-10.75,-12.525) 46(-10.25,-12.525) 47(-9.75,-12.525) 48(-9.25,-12.525) 49(-8.75,-12.525) 50(-8.25,-12.525) 51(-7.75,-12.525) 52(-7.25,-12.525) 53(-6.75,-12.525) 54(-6.25,-12.525) 55(-5.75,-12.525) 56(-5.25,-12.525) 57(-4.75,-12.525) 58(-4.25,-12.525) 59(-3.75,-12.525) 60(-3.25,-12.525) 61(-2.75,-12.525) 62(-2.25,-12.525) 63(-1.75,-12.525) 64(-1.25,-12.525) 65(-0.75,-12.525) 66(-0.25,-12.525) 67(0.25,-12.525) 68(0.75,-12.525) 69(1.25,-12.525) 70(1.75,-12.525) 71(2.25,-12.525) 72(2.75,-12.525) 73(3.25,-12.525) 74(3.75,-12.525) 75(4.25,-12.525) 76(4.75,-12.525) 77(5.25,-12.525) 78(5.75,-12.525) 79(6.25,-12.525) 80(6.75,-12.525) 81(7.25,-12.525) 82(7.75,-12.525) 83(8.25,-12.525) 84(8.75,-12.525) 85(9.25,-12.525) 86(9.75,-12.525) 87(10.25,-12.525) 88(10.75,-12.525) 133(10.75,12.525) 134(10.25,12.525) 135(9.75,12.525) 136(9.25,12.525) 137(8.75,12.525) 138(8.25,12.525) 139(7.75,12.525) 140(7.25,12.525) 141(6.75,12.525) 142(6.25,12.525) 143(5.75,12.525) 144(5.25,12.525) 145(4.75,12.525) 146(4.25,12.525) 147(3.75,12.525) 148(3.25,12.525) 149(2.75,12.525) 150(2.25,12.525) 151(1.75,12.525) 152(1.25,12.525) 153(0.75,12.525) 154(0.25,12.525) 155(-0.25,12.525) 156(-0.75,12.525) 157(-1.25,12.525) 158(-1.75,12.525) 159(-2.25,12.525) 160(-2.75,12.525) 161(-3.25,12.525) 162(-3.75,12.525) 163(-4.25,12.525) 164(-4.75,12.525) 165(-5.25,12.525) 166(-5.75,12.525) 167(-6.25,12.525) 168(-6.75,12.525) 169(-7.25,12.525) 170(-7.75,12.525) 171(-8.25,12.525) 172(-8.75,12.525) 173(-9.25,12.525) 174(-9.75,12.525) 175(-10.25,12.525) 176(-10.75,12.525)
Top Overlay:
  circle w0.6: c-10.35,10.35 r0.3
  circle w0.25: c-12.525,11.425 r0.125
  lines w0.2: -11.35,-11.35 11.35,-11.35 11.35,11.35 -11.35,11.35 -11.35,-11.35
Mechanical 13:
  circle w0.1: c-11.1,11.1 r0.5
  lines w0.1: -12,-12 12,-12 12,12 -12,12 -12,-12
Mechanical 15:
  lines w0.1: -0.5,0 0.5,0 ; 0,-0.5 0,0.5 ; -13.4,-13.4 13.4,-13.4 13.4,13.4 -13.4,13.4 -13.4,-13.4
3D body: height 1.6, standoff 0, extent -12,-12 12,12

## HTG176_M [mm] "176-Pin Heat Sink Thin Quad Flat Pack (HTG176) - Pb-Free, IPC Low Density"
height 1.6
pads (176):
  oval 2.1x0.3 smd: 1(-12.6,10.75) 2(-12.6,10.25) 3(-12.6,9.75) 4(-12.6,9.25) 5(-12.6,8.75) 6(-12.6,8.25) 7(-12.6,7.75) 8(-12.6,7.25) 9(-12.6,6.75) 10(-12.6,6.25) 11(-12.6,5.75) 12(-12.6,5.25) 13(-12.6,4.75) 14(-12.6,4.25) 15(-12.6,3.75) 16(-12.6,3.25) 17(-12.6,2.75) 18(-12.6,2.25) 19(-12.6,1.75) 20(-12.6,1.25) 21(-12.6,0.75) 22(-12.6,0.25) 23(-12.6,-0.25) 24(-12.6,-0.75) 25(-12.6,-1.25) 26(-12.6,-1.75) 27(-12.6,-2.25) 28(-12.6,-2.75) 29(-12.6,-3.25) 30(-12.6,-3.75) 31(-12.6,-4.25) 32(-12.6,-4.75) 33(-12.6,-5.25) 34(-12.6,-5.75) 35(-12.6,-6.25) 36(-12.6,-6.75) 37(-12.6,-7.25) 38(-12.6,-7.75) 39(-12.6,-8.25) 40(-12.6,-8.75) 41(-12.6,-9.25) 42(-12.6,-9.75) 43(-12.6,-10.25) 44(-12.6,-10.75) 89(12.6,-10.75) 90(12.6,-10.25) 91(12.6,-9.75) 92(12.6,-9.25) 93(12.6,-8.75) 94(12.6,-8.25) 95(12.6,-7.75) 96(12.6,-7.25) 97(12.6,-6.75) 98(12.6,-6.25) 99(12.6,-5.75) 100(12.6,-5.25) 101(12.6,-4.75) 102(12.6,-4.25) 103(12.6,-3.75) 104(12.6,-3.25) 105(12.6,-2.75) 106(12.6,-2.25) 107(12.6,-1.75) 108(12.6,-1.25) 109(12.6,-0.75) 110(12.6,-0.25) 111(12.6,0.25) 112(12.6,0.75) 113(12.6,1.25) 114(12.6,1.75) 115(12.6,2.25) 116(12.6,2.75) 117(12.6,3.25) 118(12.6,3.75) 119(12.6,4.25) 120(12.6,4.75) 121(12.6,5.25) 122(12.6,5.75) 123(12.6,6.25) 124(12.6,6.75) 125(12.6,7.25) 126(12.6,7.75) 127(12.6,8.25) 128(12.6,8.75) 129(12.6,9.25) 130(12.6,9.75) 131(12.6,10.25) 132(12.6,10.75)
  oval 0.3x2.1 smd: 45(-10.75,-12.6) 46(-10.25,-12.6) 47(-9.75,-12.6) 48(-9.25,-12.6) 49(-8.75,-12.6) 50(-8.25,-12.6) 51(-7.75,-12.6) 52(-7.25,-12.6) 53(-6.75,-12.6) 54(-6.25,-12.6) 55(-5.75,-12.6) 56(-5.25,-12.6) 57(-4.75,-12.6) 58(-4.25,-12.6) 59(-3.75,-12.6) 60(-3.25,-12.6) 61(-2.75,-12.6) 62(-2.25,-12.6) 63(-1.75,-12.6) 64(-1.25,-12.6) 65(-0.75,-12.6) 66(-0.25,-12.6) 67(0.25,-12.6) 68(0.75,-12.6) 69(1.25,-12.6) 70(1.75,-12.6) 71(2.25,-12.6) 72(2.75,-12.6) 73(3.25,-12.6) 74(3.75,-12.6) 75(4.25,-12.6) 76(4.75,-12.6) 77(5.25,-12.6) 78(5.75,-12.6) 79(6.25,-12.6) 80(6.75,-12.6) 81(7.25,-12.6) 82(7.75,-12.6) 83(8.25,-12.6) 84(8.75,-12.6) 85(9.25,-12.6) 86(9.75,-12.6) 87(10.25,-12.6) 88(10.75,-12.6) 133(10.75,12.6) 134(10.25,12.6) 135(9.75,12.6) 136(9.25,12.6) 137(8.75,12.6) 138(8.25,12.6) 139(7.75,12.6) 140(7.25,12.6) 141(6.75,12.6) 142(6.25,12.6) 143(5.75,12.6) 144(5.25,12.6) 145(4.75,12.6) 146(4.25,12.6) 147(3.75,12.6) 148(3.25,12.6) 149(2.75,12.6) 150(2.25,12.6) 151(1.75,12.6) 152(1.25,12.6) 153(0.75,12.6) 154(0.25,12.6) 155(-0.25,12.6) 156(-0.75,12.6) 157(-1.25,12.6) 158(-1.75,12.6) 159(-2.25,12.6) 160(-2.75,12.6) 161(-3.25,12.6) 162(-3.75,12.6) 163(-4.25,12.6) 164(-4.75,12.6) 165(-5.25,12.6) 166(-5.75,12.6) 167(-6.25,12.6) 168(-6.75,12.6) 169(-7.25,12.6) 170(-7.75,12.6) 171(-8.25,12.6) 172(-8.75,12.6) 173(-9.25,12.6) 174(-9.75,12.6) 175(-10.25,12.6) 176(-10.75,12.6)
Top Overlay:
  circle w0.6: c-10.15,10.15 r0.3
  circle w0.25: c-12.6,11.45 r0.125
  lines w0.2: -11.15,-11.15 11.15,-11.15 11.15,11.15 -11.15,11.15 -11.15,-11.15
Mechanical 13:
  circle w0.1: c-11.1,11.1 r0.5
  lines w0.1: -12,-12 12,-12 12,12 -12,12 -12,-12
Mechanical 15:
  lines w0.1: -0.5,0 0.5,0 ; 0,-0.5 0,0.5 ; -14.15,-14.15 14.15,-14.15 14.15,14.15 -14.15,14.15 -14.15,-14.15
3D body: height 1.6, standoff 0, extent -12,-12 12,12

## HTG176_N [mm] "176-Pin Heat Sink Thin Quad Flat Pack (HTG176) - Pb-Free, IPC Medium Density"
height 1.6
pads (176):
  oval 1.8x0.3 smd: 1(-12.55,10.75) 2(-12.55,10.25) 3(-12.55,9.75) 4(-12.55,9.25) 5(-12.55,8.75) 6(-12.55,8.25) 7(-12.55,7.75) 8(-12.55,7.25) 9(-12.55,6.75) 10(-12.55,6.25) 11(-12.55,5.75) 12(-12.55,5.25) 13(-12.55,4.75) 14(-12.55,4.25) 15(-12.55,3.75) 16(-12.55,3.25) 17(-12.55,2.75) 18(-12.55,2.25) 19(-12.55,1.75) 20(-12.55,1.25) 21(-12.55,0.75) 22(-12.55,0.25) 23(-12.55,-0.25) 24(-12.55,-0.75) 25(-12.55,-1.25) 26(-12.55,-1.75) 27(-12.55,-2.25) 28(-12.55,-2.75) 29(-12.55,-3.25) 30(-12.55,-3.75) 31(-12.55,-4.25) 32(-12.55,-4.75) 33(-12.55,-5.25) 34(-12.55,-5.75) 35(-12.55,-6.25) 36(-12.55,-6.75) 37(-12.55,-7.25) 38(-12.55,-7.75) 39(-12.55,-8.25) 40(-12.55,-8.75) 41(-12.55,-9.25) 42(-12.55,-9.75) 43(-12.55,-10.25) 44(-12.55,-10.75) 89(12.55,-10.75) 90(12.55,-10.25) 91(12.55,-9.75) 92(12.55,-9.25) 93(12.55,-8.75) 94(12.55,-8.25) 95(12.55,-7.75) 96(12.55,-7.25) 97(12.55,-6.75) 98(12.55,-6.25) 99(12.55,-5.75) 100(12.55,-5.25) 101(12.55,-4.75) 102(12.55,-4.25) 103(12.55,-3.75) 104(12.55,-3.25) 105(12.55,-2.75) 106(12.55,-2.25) 107(12.55,-1.75) 108(12.55,-1.25) 109(12.55,-0.75) 110(12.55,-0.25) 111(12.55,0.25) 112(12.55,0.75) 113(12.55,1.25) 114(12.55,1.75) 115(12.55,2.25) 116(12.55,2.75) 117(12.55,3.25) 118(12.55,3.75) 119(12.55,4.25) 120(12.55,4.75) 121(12.55,5.25) 122(12.55,5.75) 123(12.55,6.25) 124(12.55,6.75) 125(12.55,7.25) 126(12.55,7.75) 127(12.55,8.25) 128(12.55,8.75) 129(12.55,9.25) 130(12.55,9.75) 131(12.55,10.25) 132(12.55,10.75)
  oval 0.3x1.8 smd: 45(-10.75,-12.55) 46(-10.25,-12.55) 47(-9.75,-12.55) 48(-9.25,-12.55) 49(-8.75,-12.55) 50(-8.25,-12.55) 51(-7.75,-12.55) 52(-7.25,-12.55) 53(-6.75,-12.55) 54(-6.25,-12.55) 55(-5.75,-12.55) 56(-5.25,-12.55) 57(-4.75,-12.55) 58(-4.25,-12.55) 59(-3.75,-12.55) 60(-3.25,-12.55) 61(-2.75,-12.55) 62(-2.25,-12.55) 63(-1.75,-12.55) 64(-1.25,-12.55) 65(-0.75,-12.55) 66(-0.25,-12.55) 67(0.25,-12.55) 68(0.75,-12.55) 69(1.25,-12.55) 70(1.75,-12.55) 71(2.25,-12.55) 72(2.75,-12.55) 73(3.25,-12.55) 74(3.75,-12.55) 75(4.25,-12.55) 76(4.75,-12.55) 77(5.25,-12.55) 78(5.75,-12.55) 79(6.25,-12.55) 80(6.75,-12.55) 81(7.25,-12.55) 82(7.75,-12.55) 83(8.25,-12.55) 84(8.75,-12.55) 85(9.25,-12.55) 86(9.75,-12.55) 87(10.25,-12.55) 88(10.75,-12.55) 133(10.75,12.55) 134(10.25,12.55) 135(9.75,12.55) 136(9.25,12.55) 137(8.75,12.55) 138(8.25,12.55) 139(7.75,12.55) 140(7.25,12.55) 141(6.75,12.55) 142(6.25,12.55) 143(5.75,12.55) 144(5.25,12.55) 145(4.75,12.55) 146(4.25,12.55) 147(3.75,12.55) 148(3.25,12.55) 149(2.75,12.55) 150(2.25,12.55) 151(1.75,12.55) 152(1.25,12.55) 153(0.75,12.55) 154(0.25,12.55) 155(-0.25,12.55) 156(-0.75,12.55) 157(-1.25,12.55) 158(-1.75,12.55) 159(-2.25,12.55) 160(-2.75,12.55) 161(-3.25,12.55) 162(-3.75,12.55) 163(-4.25,12.55) 164(-4.75,12.55) 165(-5.25,12.55) 166(-5.75,12.55) 167(-6.25,12.55) 168(-6.75,12.55) 169(-7.25,12.55) 170(-7.75,12.55) 171(-8.25,12.55) 172(-8.75,12.55) 173(-9.25,12.55) 174(-9.75,12.55) 175(-10.25,12.55) 176(-10.75,12.55)
Top Overlay:
  circle w0.25: c-12.55,11.45 r0.125
  circle w0.6: c-10.25,10.25 r0.3
  lines w0.2: -11.25,-11.25 -11.25,11.25 11.25,11.25 11.25,-11.25 -11.25,-11.25
Mechanical 13:
  circle w0.1: c-11.1,11.1 r0.5
  lines w0.1: -12,-12 -12,12 12,12 12,-12 -12,-12
Mechanical 15:
  lines w0.1: -0.5,0 0.5,0 ; 0,-0.5 0,0.5 ; -13.7,-13.7 -13.7,13.7 13.7,13.7 13.7,-13.7 -13.7,-13.7
3D body: height 1.6, standoff 0, extent -12,-12 12,12

## MQ208_L [mm] "208-Pin Metal Quad Flat Pack (MQ208), IPC High Density"
height 4.1
pads (208):
  oval 1.55x0.25 smd: 1(-14.825,12.75) 2(-14.825,12.25) 3(-14.825,11.75) 4(-14.825,11.25) 5(-14.825,10.75) 6(-14.825,10.25) 7(-14.825,9.75) 8(-14.825,9.25) 9(-14.825,8.75) 10(-14.825,8.25) 11(-14.825,7.75) 12(-14.825,7.25) 13(-14.825,6.75) 14(-14.825,6.25) 15(-14.825,5.75) 16(-14.825,5.25) 17(-14.825,4.75) 18(-14.825,4.25) 19(-14.825,3.75) 20(-14.825,3.25) 21(-14.825,2.75) 22(-14.825,2.25) 23(-14.825,1.75) 24(-14.825,1.25) 25(-14.825,0.75) 26(-14.825,0.25) 27(-14.825,-0.25) 28(-14.825,-0.75) 29(-14.825,-1.25) 30(-14.825,-1.75) 31(-14.825,-2.25) 32(-14.825,-2.75) 33(-14.825,-3.25) 34(-14.825,-3.75) 35(-14.825,-4.25) 36(-14.825,-4.75) 37(-14.825,-5.25) 38(-14.825,-5.75) 39(-14.825,-6.25) 40(-14.825,-6.75) 41(-14.825,-7.25) 42(-14.825,-7.75) 43(-14.825,-8.25) 44(-14.825,-8.75) 45(-14.825,-9.25) 46(-14.825,-9.75) 47(-14.825,-10.25) 48(-14.825,-10.75) 49(-14.825,-11.25) 50(-14.825,-11.75) 51(-14.825,-12.25) 52(-14.825,-12.75) 105(14.825,-12.75) 106(14.825,-12.25) 107(14.825,-11.75) 108(14.825,-11.25) 109(14.825,-10.75) 110(14.825,-10.25) 111(14.825,-9.75) 112(14.825,-9.25) 113(14.825,-8.75) 114(14.825,-8.25) 115(14.825,-7.75) 116(14.825,-7.25) 117(14.825,-6.75) 118(14.825,-6.25) 119(14.825,-5.75) 120(14.825,-5.25) 121(14.825,-4.75) 122(14.825,-4.25) 123(14.825,-3.75) 124(14.825,-3.25) 125(14.825,-2.75) 126(14.825,-2.25) 127(14.825,-1.75) 128(14.825,-1.25) 129(14.825,-0.75) 130(14.825,-0.25) 131(14.825,0.25) 132(14.825,0.75) 133(14.825,1.25) 134(14.825,1.75) 135(14.825,2.25) 136(14.825,2.75) 137(14.825,3.25) 138(14.825,3.75) 139(14.825,4.25) 140(14.825,4.75) 141(14.825,5.25) 142(14.825,5.75) 143(14.825,6.25) 144(14.825,6.75) 145(14.825,7.25) 146(14.825,7.75) 147(14.825,8.25) 148(14.825,8.75) 149(14.825,9.25) 150(14.825,9.75) 151(14.825,10.25) 152(14.825,10.75) 153(14.825,11.25) 154(14.825,11.75) 155(14.825,12.25) 156(14.825,12.75)
  oval 0.25x1.55 smd: 53(-12.75,-14.825) 54(-12.25,-14.825) 55(-11.75,-14.825) 56(-11.25,-14.825) 57(-10.75,-14.825) 58(-10.25,-14.825) 59(-9.75,-14.825) 60(-9.25,-14.825) 61(-8.75,-14.825) 62(-8.25,-14.825) 63(-7.75,-14.825) 64(-7.25,-14.825) 65(-6.75,-14.825) 66(-6.25,-14.825) 67(-5.75,-14.825) 68(-5.25,-14.825) 69(-4.75,-14.825) 70(-4.25,-14.825) 71(-3.75,-14.825) 72(-3.25,-14.825) 73(-2.75,-14.825) 74(-2.25,-14.825) 75(-1.75,-14.825) 76(-1.25,-14.825) 77(-0.75,-14.825) 78(-0.25,-14.825) 79(0.25,-14.825) 80(0.75,-14.825) 81(1.25,-14.825) 82(1.75,-14.825) 83(2.25,-14.825) 84(2.75,-14.825) 85(3.25,-14.825) 86(3.75,-14.825) 87(4.25,-14.825) 88(4.75,-14.825) 89(5.25,-14.825) 90(5.75,-14.825) 91(6.25,-14.825) 92(6.75,-14.825) 93(7.25,-14.825) 94(7.75,-14.825) 95(8.25,-14.825) 96(8.75,-14.825) 97(9.25,-14.825) 98(9.75,-14.825) 99(10.25,-14.825) 100(10.75,-14.825) 101(11.25,-14.825) 102(11.75,-14.825) 103(12.25,-14.825) 104(12.75,-14.825) 157(12.75,14.825) 158(12.25,14.825) 159(11.75,14.825) 160(11.25,14.825) 161(10.75,14.825) 162(10.25,14.825) 163(9.75,14.825) 164(9.25,14.825) 165(8.75,14.825) 166(8.25,14.825) 167(7.75,14.825) 168(7.25,14.825) 169(6.75,14.825) 170(6.25,14.825) 171(5.75,14.825) 172(5.25,14.825) 173(4.75,14.825) 174(4.25,14.825) 175(3.75,14.825) 176(3.25,14.825) 177(2.75,14.825) 178(2.25,14.825) 179(1.75,14.825) 180(1.25,14.825) 181(0.75,14.825) 182(0.25,14.825) 183(-0.25,14.825) 184(-0.75,14.825) 185(-1.25,14.825) 186(-1.75,14.825) 187(-2.25,14.825) 188(-2.75,14.825) 189(-3.25,14.825) 190(-3.75,14.825) 191(-4.25,14.825) 192(-4.75,14.825) 193(-5.25,14.825) 194(-5.75,14.825) 195(-6.25,14.825) 196(-6.75,14.825) 197(-7.25,14.825) 198(-7.75,14.825) 199(-8.25,14.825) 200(-8.75,14.825) 201(-9.25,14.825) 202(-9.75,14.825) 203(-10.25,14.825) 204(-10.75,14.825) 205(-11.25,14.825) 206(-11.75,14.825) 207(-12.25,14.825) 208(-12.75,14.825)
Top Overlay:
  circle w0.25: c-14.825,13.425 r0.125
  circle w0.6: c-12.65,12.65 r0.3
  lines w0.2: -13.65,-13.65 -13.65,13.65 13.65,13.65 13.65,-13.65 -13.65,-13.65
Mechanical 13:
  circle w0.1: c-13.1,13.1 r0.5
  lines w0.1: -14,-14 -14,14 14,14 14,-14 -14,-14
Mechanical 15:
  lines w0.1: -0.5,0 0.5,0 ; 0,-0.5 0,0.5 ; -15.7,-15.7 -15.7,15.7 15.7,15.7 15.7,-15.7 -15.7,-15.7
3D body: height 4.1, standoff 0, extent -14,-14 14,14

## MQ208_M [mm] "208-Pin Metal Quad Flat Pack (MQ208), IPC Low Density"
height 4.1
pads (208):
  oval 2.1x0.3 smd: 1(-14.9,12.75) 2(-14.9,12.25) 3(-14.9,11.75) 4(-14.9,11.25) 5(-14.9,10.75) 6(-14.9,10.25) 7(-14.9,9.75) 8(-14.9,9.25) 9(-14.9,8.75) 10(-14.9,8.25) 11(-14.9,7.75) 12(-14.9,7.25) 13(-14.9,6.75) 14(-14.9,6.25) 15(-14.9,5.75) 16(-14.9,5.25) 17(-14.9,4.75) 18(-14.9,4.25) 19(-14.9,3.75) 20(-14.9,3.25) 21(-14.9,2.75) 22(-14.9,2.25) 23(-14.9,1.75) 24(-14.9,1.25) 25(-14.9,0.75) 26(-14.9,0.25) 27(-14.9,-0.25) 28(-14.9,-0.75) 29(-14.9,-1.25) 30(-14.9,-1.75) 31(-14.9,-2.25) 32(-14.9,-2.75) 33(-14.9,-3.25) 34(-14.9,-3.75) 35(-14.9,-4.25) 36(-14.9,-4.75) 37(-14.9,-5.25) 38(-14.9,-5.75) 39(-14.9,-6.25) 40(-14.9,-6.75) 41(-14.9,-7.25) 42(-14.9,-7.75) 43(-14.9,-8.25) 44(-14.9,-8.75) 45(-14.9,-9.25) 46(-14.9,-9.75) 47(-14.9,-10.25) 48(-14.9,-10.75) 49(-14.9,-11.25) 50(-14.9,-11.75) 51(-14.9,-12.25) 52(-14.9,-12.75) 105(14.9,-12.75) 106(14.9,-12.25) 107(14.9,-11.75) 108(14.9,-11.25) 109(14.9,-10.75) 110(14.9,-10.25) 111(14.9,-9.75) 112(14.9,-9.25) 113(14.9,-8.75) 114(14.9,-8.25) 115(14.9,-7.75) 116(14.9,-7.25) 117(14.9,-6.75) 118(14.9,-6.25) 119(14.9,-5.75) 120(14.9,-5.25) 121(14.9,-4.75) 122(14.9,-4.25) 123(14.9,-3.75) 124(14.9,-3.25) 125(14.9,-2.75) 126(14.9,-2.25) 127(14.9,-1.75) 128(14.9,-1.25) 129(14.9,-0.75) 130(14.9,-0.25) 131(14.9,0.25) 132(14.9,0.75) 133(14.9,1.25) 134(14.9,1.75) 135(14.9,2.25) 136(14.9,2.75) 137(14.9,3.25) 138(14.9,3.75) 139(14.9,4.25) 140(14.9,4.75) 141(14.9,5.25) 142(14.9,5.75) 143(14.9,6.25) 144(14.9,6.75) 145(14.9,7.25) 146(14.9,7.75) 147(14.9,8.25) 148(14.9,8.75) 149(14.9,9.25) 150(14.9,9.75) 151(14.9,10.25) 152(14.9,10.75) 153(14.9,11.25) 154(14.9,11.75) 155(14.9,12.25) 156(14.9,12.75)
  oval 0.3x2.1 smd: 53(-12.75,-14.9) 54(-12.25,-14.9) 55(-11.75,-14.9) 56(-11.25,-14.9) 57(-10.75,-14.9) 58(-10.25,-14.9) 59(-9.75,-14.9) 60(-9.25,-14.9) 61(-8.75,-14.9) 62(-8.25,-14.9) 63(-7.75,-14.9) 64(-7.25,-14.9) 65(-6.75,-14.9) 66(-6.25,-14.9) 67(-5.75,-14.9) 68(-5.25,-14.9) 69(-4.75,-14.9) 70(-4.25,-14.9) 71(-3.75,-14.9) 72(-3.25,-14.9) 73(-2.75,-14.9) 74(-2.25,-14.9) 75(-1.75,-14.9) 76(-1.25,-14.9) 77(-0.75,-14.9) 78(-0.25,-14.9) 79(0.25,-14.9) 80(0.75,-14.9) 81(1.25,-14.9) 82(1.75,-14.9) 83(2.25,-14.9) 84(2.75,-14.9) 85(3.25,-14.9) 86(3.75,-14.9) 87(4.25,-14.9) 88(4.75,-14.9) 89(5.25,-14.9) 90(5.75,-14.9) 91(6.25,-14.9) 92(6.75,-14.9) 93(7.25,-14.9) 94(7.75,-14.9) 95(8.25,-14.9) 96(8.75,-14.9) 97(9.25,-14.9) 98(9.75,-14.9) 99(10.25,-14.9) 100(10.75,-14.9) 101(11.25,-14.9) 102(11.75,-14.9) 103(12.25,-14.9) 104(12.75,-14.9) 157(12.75,14.9) 158(12.25,14.9) 159(11.75,14.9) 160(11.25,14.9) 161(10.75,14.9) 162(10.25,14.9) 163(9.75,14.9) 164(9.25,14.9) 165(8.75,14.9) 166(8.25,14.9) 167(7.75,14.9) 168(7.25,14.9) 169(6.75,14.9) 170(6.25,14.9) 171(5.75,14.9) 172(5.25,14.9) 173(4.75,14.9) 174(4.25,14.9) 175(3.75,14.9) 176(3.25,14.9) 177(2.75,14.9) 178(2.25,14.9) 179(1.75,14.9) 180(1.25,14.9) 181(0.75,14.9) 182(0.25,14.9) 183(-0.25,14.9) 184(-0.75,14.9) 185(-1.25,14.9) 186(-1.75,14.9) 187(-2.25,14.9) 188(-2.75,14.9) 189(-3.25,14.9) 190(-3.75,14.9) 191(-4.25,14.9) 192(-4.75,14.9) 193(-5.25,14.9) 194(-5.75,14.9) 195(-6.25,14.9) 196(-6.75,14.9) 197(-7.25,14.9) 198(-7.75,14.9) 199(-8.25,14.9) 200(-8.75,14.9) 201(-9.25,14.9) 202(-9.75,14.9) 203(-10.25,14.9) 204(-10.75,14.9) 205(-11.25,14.9) 206(-11.75,14.9) 207(-12.25,14.9) 208(-12.75,14.9)
Top Overlay:
  circle w0.6: c-12.45,12.45 r0.3
  circle w0.25: c-14.9,13.45 r0.125
  lines w0.2: -13.45,-13.45 13.45,-13.45 13.45,13.45 -13.45,13.45 -13.45,-13.45
Mechanical 13:
  circle w0.1: c-13.1,13.1 r0.5
  lines w0.1: -14,-14 14,-14 14,14 -14,14 -14,-14
Mechanical 15:
  lines w0.1: -0.5,0 0.5,0 ; 0,-0.5 0,0.5 ; -16.45,-16.45 16.45,-16.45 16.45,16.45 -16.45,16.45 -16.45,-16.45
3D body: height 4.1, standoff 0, extent -14,-14 14,14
